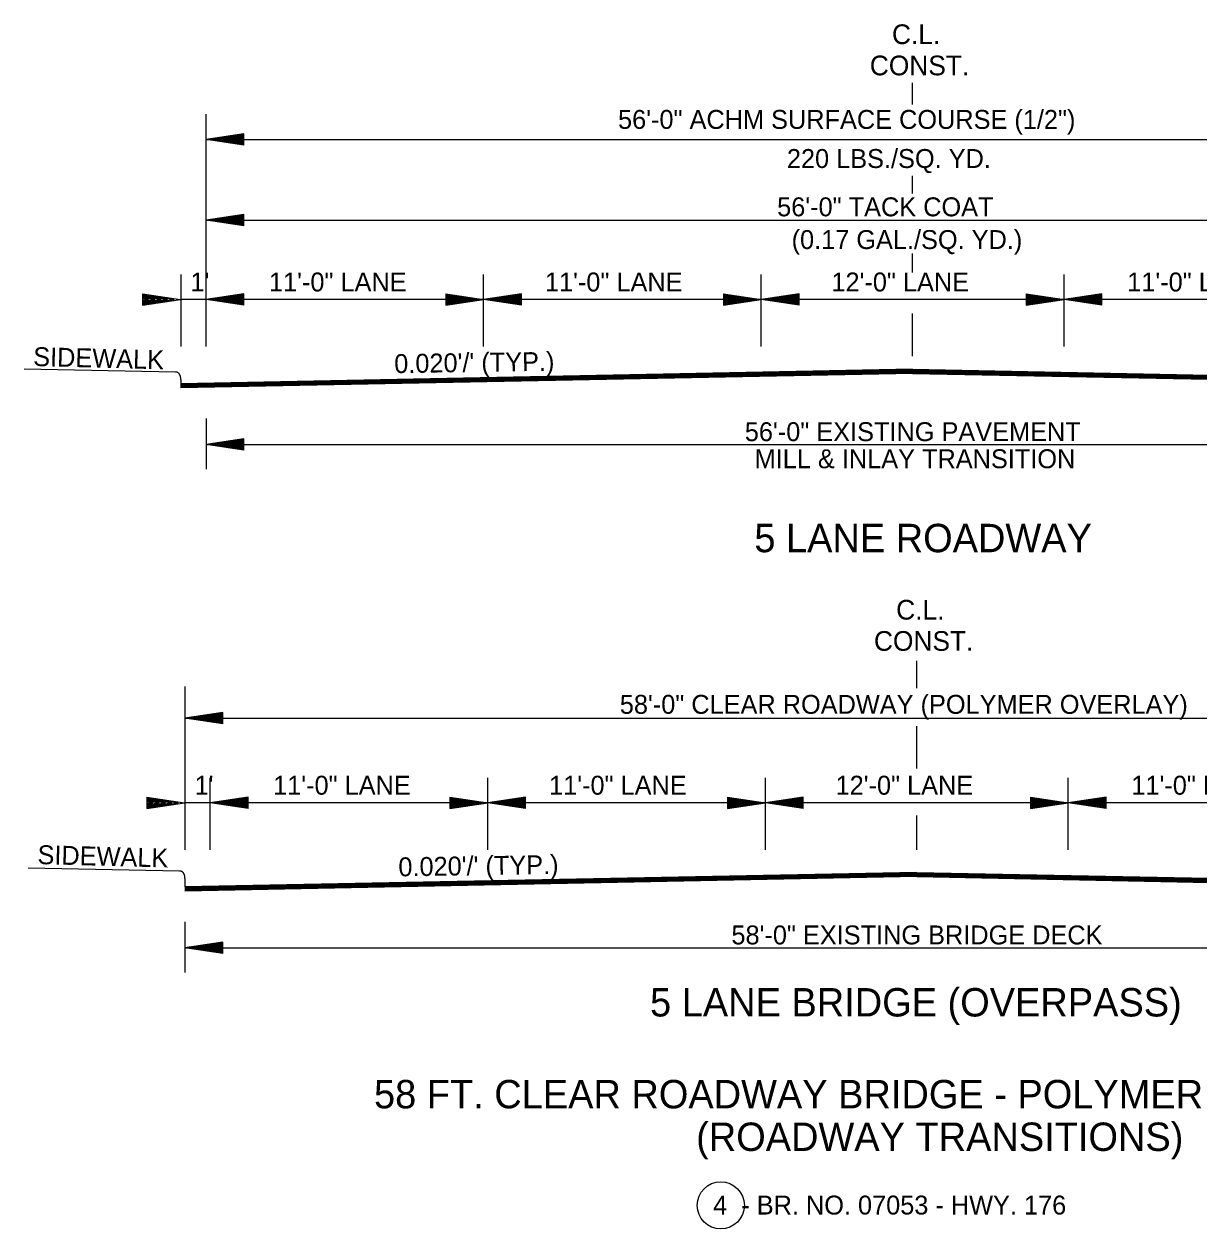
# Model space of a CAD drawing. Extents: x 544199 to 1930787, y -1968972 to 596640.
# Drawn here: x 546380.5 to 546846, y -1949089.3 to -1948612 of the extents above; entities that cross this region are included whole.
import ezdxf

# ---------------------------------------------------------------- set-up
doc = ezdxf.new("R2010")
doc.units = 0
doc.layers.add('R_Border', color=7, linetype='Continuous')
doc.layers.add('R_Draft', color=7, linetype='Continuous')

msp = doc.modelspace()

# ---------------------------------------------------------------- linework, layer by layer
at = {"layer": 'R_Border'}
for p, q in [((546440.43, -1948749.86), (546380.49, -1948748.73)), ((546442.07, -1948947.55), (546382.13, -1948946.43))]:
    msp.add_line(p, q, dxfattribs=at)
msp.add_circle((546656.55, -1949080), 9.34, dxfattribs=at)
for points in [[(546442.58, -1948752.84), (546442.5, -1948749.9), (546440.43, -1948749.86)], [(546444.22, -1948950.54), (546444.14, -1948947.59), (546442.07, -1948947.55)]]:
    msp.add_open_spline(points, degree=2, dxfattribs=at)
at = {"layer": 'R_Draft'}
for p, q in [((546732.58, -1948643.93), (546732.58, -1948635.31)), ((546452.58, -1948739.77), (546452.58, -1948647.75)), ((546467.58, -1948655.51), (546452.58, -1948657.76)), ((546467.58, -1948655.89), (546455.09, -1948657.76)), ((546467.58, -1948656.27), (546457.67, -1948657.76)), ((546467.58, -1948656.65), (546460.16, -1948657.76)), ((546467.58, -1948657.03), (546462.71, -1948657.76)), ((546467.58, -1948657.41), (546465.21, -1948657.76)), ((546467.58, -1948660.01), (546467.58, -1948655.51)), ((546452.58, -1948657.76), (547012.58, -1948657.76)), ((546467.58, -1948660.01), (546452.58, -1948657.76)), ((546467.58, -1948659.64), (546455.09, -1948657.76)), ((546467.58, -1948659.26), (546457.67, -1948657.76)), ((546467.58, -1948658.88), (546460.16, -1948657.76)), ((546467.58, -1948658.49), (546462.71, -1948657.76)), ((546467.58, -1948658.12), (546465.21, -1948657.76)), ((546732.58, -1948679.11), (546732.58, -1948672.11)), ((546467.58, -1948687.41), (546452.58, -1948689.66)), ((546452.58, -1948689.66), (547012.58, -1948689.66)), ((546467.58, -1948691.91), (546452.58, -1948689.66)), ((546467.58, -1948687.79), (546455.09, -1948689.66)), ((546467.58, -1948691.54), (546455.09, -1948689.66)), ((546467.58, -1948688.17), (546457.67, -1948689.66)), ((546467.58, -1948691.16), (546457.67, -1948689.66)), ((546467.58, -1948688.55), (546460.16, -1948689.66)), ((546467.58, -1948690.78), (546460.16, -1948689.66)), ((546467.58, -1948688.93), (546462.71, -1948689.66)), ((546467.58, -1948690.39), (546462.71, -1948689.66)), ((546467.58, -1948689.31), (546465.21, -1948689.66)), ((546467.58, -1948690.02), (546465.21, -1948689.66)), ((546467.58, -1948691.91), (546467.58, -1948687.41)), ((546732.58, -1948710.44), (546732.58, -1948702.92)), ((546442.58, -1948711.22), (546442.58, -1948739.77)), ((546562.58, -1948739.77), (546562.58, -1948711.22)), ((546672.58, -1948739.77), (546672.58, -1948711.22)), ((546792.58, -1948739.77), (546792.58, -1948711.22)), ((546427.46, -1948718.86), (546442.46, -1948721.11)), ((546427.46, -1948718.86), (546427.46, -1948723.36)), ((546427.46, -1948719.23), (546439.95, -1948721.11)), ((546467.58, -1948718.86), (546452.58, -1948721.11)), ((546467.58, -1948719.23), (546455.09, -1948721.11)), ((546467.58, -1948723.36), (546467.58, -1948718.86)), ((546547.58, -1948718.86), (546562.58, -1948721.11)), ((546547.58, -1948718.86), (546547.58, -1948723.36)), ((546547.58, -1948719.23), (546560.08, -1948721.11)), ((546577.58, -1948718.86), (546562.58, -1948721.11)), ((546577.58, -1948719.23), (546565.09, -1948721.11)), ((546577.58, -1948723.36), (546577.58, -1948718.86)), ((546657.58, -1948718.86), (546672.58, -1948721.11)), ((546657.58, -1948718.86), (546657.58, -1948723.36)), ((546657.58, -1948719.23), (546670.08, -1948721.11)), ((546687.58, -1948718.86), (546672.58, -1948721.11)), ((546687.58, -1948719.23), (546675.09, -1948721.11)), ((546687.58, -1948723.36), (546687.58, -1948718.86)), ((546777.58, -1948718.86), (546792.58, -1948721.11)), ((546777.58, -1948718.86), (546777.58, -1948723.36)), ((546777.58, -1948719.23), (546790.08, -1948721.11)), ((546807.58, -1948718.86), (546792.58, -1948721.11)), ((546807.58, -1948719.23), (546795.09, -1948721.11)), ((546807.58, -1948723.36), (546807.58, -1948718.86)), ((546427.46, -1948719.62), (546437.37, -1948721.11)), ((546427.46, -1948719.99), (546434.87, -1948721.11)), ((546427.46, -1948720.38), (546432.33, -1948721.11)), ((546427.46, -1948720.76), (546429.83, -1948721.11)), ((546427.46, -1948723.36), (546442.46, -1948721.11)), ((546427.46, -1948721.84), (546432.33, -1948721.11)), ((546427.46, -1948722.6), (546437.37, -1948721.11)), ((546427.46, -1948722.98), (546439.95, -1948721.11)), ((546427.46, -1948722.23), (546434.87, -1948721.11)), ((546427.46, -1948721.46), (546429.83, -1948721.11)), ((546542.58, -1948721.11), (546442.58, -1948721.11)), ((546467.58, -1948723.36), (546452.58, -1948721.11)), ((546467.58, -1948722.98), (546455.09, -1948721.11)), ((546467.58, -1948719.62), (546457.67, -1948721.11)), ((546467.58, -1948722.6), (546457.67, -1948721.11)), ((546467.58, -1948719.99), (546460.16, -1948721.11)), ((546467.58, -1948722.23), (546460.16, -1948721.11)), ((546467.58, -1948720.37), (546462.71, -1948721.11)), ((546467.58, -1948721.84), (546462.71, -1948721.11)), ((546467.58, -1948720.76), (546465.21, -1948721.11)), ((546467.58, -1948721.46), (546465.21, -1948721.11)), ((546672.58, -1948721.11), (546542.58, -1948721.11)), ((546547.58, -1948719.62), (546557.5, -1948721.11)), ((546547.58, -1948719.99), (546555, -1948721.11)), ((546547.58, -1948720.38), (546552.46, -1948721.11)), ((546547.58, -1948720.76), (546549.95, -1948721.11)), ((546547.58, -1948723.36), (546562.58, -1948721.11)), ((546547.58, -1948721.84), (546552.46, -1948721.11)), ((546547.58, -1948722.6), (546557.5, -1948721.11)), ((546547.58, -1948722.98), (546560.08, -1948721.11)), ((546547.58, -1948722.23), (546555, -1948721.11)), ((546547.58, -1948721.46), (546549.95, -1948721.11)), ((546577.58, -1948723.36), (546562.58, -1948721.11)), ((546577.58, -1948722.98), (546565.09, -1948721.11)), ((546577.58, -1948719.62), (546567.67, -1948721.11)), ((546577.58, -1948722.6), (546567.67, -1948721.11)), ((546577.58, -1948719.99), (546570.16, -1948721.11)), ((546577.58, -1948722.23), (546570.16, -1948721.11)), ((546577.58, -1948720.37), (546572.71, -1948721.11)), ((546577.58, -1948721.84), (546572.71, -1948721.11)), ((546577.58, -1948720.76), (546575.21, -1948721.11)), ((546577.58, -1948721.46), (546575.21, -1948721.11)), ((546657.58, -1948719.62), (546667.5, -1948721.11)), ((546657.58, -1948719.99), (546665, -1948721.11)), ((546657.58, -1948720.38), (546662.46, -1948721.11)), ((546657.58, -1948720.76), (546659.95, -1948721.11)), ((546657.58, -1948723.36), (546672.58, -1948721.11)), ((546657.58, -1948721.84), (546662.46, -1948721.11)), ((546657.58, -1948722.6), (546667.5, -1948721.11)), ((546657.58, -1948722.98), (546670.08, -1948721.11)), ((546657.58, -1948722.23), (546665, -1948721.11)), ((546657.58, -1948721.46), (546659.95, -1948721.11)), ((546792.58, -1948721.11), (546672.58, -1948721.11)), ((546687.58, -1948723.36), (546672.58, -1948721.11)), ((546687.58, -1948722.98), (546675.09, -1948721.11)), ((546687.58, -1948719.62), (546677.67, -1948721.11)), ((546687.58, -1948722.6), (546677.67, -1948721.11)), ((546687.58, -1948719.99), (546680.16, -1948721.11)), ((546687.58, -1948722.23), (546680.16, -1948721.11)), ((546687.58, -1948720.37), (546682.71, -1948721.11)), ((546687.58, -1948721.84), (546682.71, -1948721.11)), ((546687.58, -1948720.76), (546685.21, -1948721.11)), ((546687.58, -1948721.46), (546685.21, -1948721.11)), ((546777.58, -1948719.62), (546787.5, -1948721.11)), ((546777.58, -1948719.99), (546785, -1948721.11)), ((546777.58, -1948720.38), (546782.46, -1948721.11)), ((546777.58, -1948720.76), (546779.95, -1948721.11)), ((546777.58, -1948723.36), (546792.58, -1948721.11)), ((546777.58, -1948721.84), (546782.46, -1948721.11)), ((546777.58, -1948722.6), (546787.5, -1948721.11)), ((546777.58, -1948722.98), (546790.08, -1948721.11)), ((546777.58, -1948722.23), (546785, -1948721.11)), ((546777.58, -1948721.46), (546779.95, -1948721.11)), ((546922.58, -1948721.11), (546792.58, -1948721.11)), ((546807.58, -1948723.36), (546792.58, -1948721.11)), ((546807.58, -1948722.98), (546795.09, -1948721.11)), ((546807.58, -1948719.62), (546797.67, -1948721.11)), ((546807.58, -1948722.6), (546797.67, -1948721.11)), ((546807.58, -1948719.99), (546800.16, -1948721.11)), ((546807.58, -1948722.23), (546800.16, -1948721.11)), ((546807.58, -1948720.37), (546802.71, -1948721.11)), ((546807.58, -1948721.84), (546802.71, -1948721.11)), ((546807.58, -1948720.76), (546805.21, -1948721.11)), ((546807.58, -1948721.46), (546805.21, -1948721.11)), ((546732.58, -1948743.55), (546732.58, -1948726.65)), ((546732.58, -1948748.72), (546442.58, -1948754.52)), ((546732.59, -1948749.02), (546442.58, -1948754.82)), ((546732.59, -1948749.32), (546442.58, -1948755.12)), ((546732.6, -1948749.62), (546442.58, -1948755.42)), ((546732.6, -1948749.92), (546442.58, -1948755.72)), ((546732.61, -1948750.22), (546442.58, -1948756.02)), ((546732.61, -1948750.39), (546442.58, -1948756.19)), ((546442.58, -1948752.84), (546442.58, -1948754.52)), ((546732.55, -1948750.22), (547022.58, -1948756.02)), ((546732.55, -1948750.39), (547022.58, -1948756.19)), ((546732.56, -1948749.62), (547022.58, -1948755.42)), ((546732.56, -1948749.92), (547022.58, -1948755.72)), ((546732.57, -1948749.02), (547022.58, -1948754.82)), ((546732.57, -1948749.32), (547022.58, -1948755.12)), ((546732.58, -1948748.72), (547022.58, -1948754.52)), ((546442.58, -1948754.52), (546442.58, -1948756.19)), ((546452.61, -1948768.32), (546452.61, -1948788.32)), ((546467.58, -1948776.32), (546452.58, -1948778.57)), ((546467.58, -1948776.7), (546455.09, -1948778.57)), ((546467.58, -1948780.82), (546467.58, -1948776.32)), ((546452.58, -1948778.57), (547012.58, -1948778.57)), ((546467.58, -1948780.82), (546452.58, -1948778.57)), ((546467.58, -1948780.45), (546455.09, -1948778.57)), ((546467.58, -1948777.08), (546457.67, -1948778.57)), ((546467.58, -1948780.07), (546457.67, -1948778.57)), ((546467.58, -1948777.46), (546460.16, -1948778.57)), ((546467.58, -1948779.69), (546460.16, -1948778.57)), ((546467.58, -1948777.84), (546462.71, -1948778.57)), ((546467.58, -1948779.3), (546462.71, -1948778.57)), ((546467.58, -1948778.22), (546465.21, -1948778.57)), ((546467.58, -1948778.93), (546465.21, -1948778.57)), ((546734.22, -1948875.08), (546734.22, -1948864.22)), ((546444.22, -1948874.41), (546444.22, -1948939.14)), ((546459.22, -1948884.69), (546444.22, -1948886.94)), ((546459.22, -1948885.06), (546446.73, -1948886.94)), ((546459.22, -1948885.45), (546449.31, -1948886.94)), ((546459.22, -1948885.82), (546451.81, -1948886.94)), ((546459.22, -1948886.2), (546454.35, -1948886.94)), ((546459.22, -1948886.59), (546456.85, -1948886.94)), ((546459.22, -1948889.19), (546459.22, -1948884.69)), ((546444.22, -1948886.94), (547024.22, -1948886.94)), ((546459.22, -1948889.19), (546444.22, -1948886.94)), ((546459.22, -1948888.81), (546446.73, -1948886.94)), ((546459.22, -1948888.43), (546449.31, -1948886.94)), ((546459.22, -1948888.06), (546451.81, -1948886.94)), ((546459.22, -1948887.67), (546454.35, -1948886.94)), ((546459.22, -1948887.29), (546456.85, -1948886.94)), ((546734.22, -1948907), (546734.22, -1948890.1)), ((546454.22, -1948939.14), (546454.22, -1948910.58)), ((546564.22, -1948939.14), (546564.22, -1948910.58)), ((546674.22, -1948939.14), (546674.22, -1948910.58)), ((546794.22, -1948939.14), (546794.22, -1948910.58)), ((546429.1, -1948918.23), (546444.1, -1948920.48)), ((546429.1, -1948918.23), (546429.1, -1948922.73)), ((546429.1, -1948918.6), (546441.59, -1948920.48)), ((546429.1, -1948918.98), (546439.01, -1948920.48)), ((546429.1, -1948919.36), (546436.52, -1948920.48)), ((546429.1, -1948919.75), (546433.97, -1948920.48)), ((546469.22, -1948918.23), (546454.22, -1948920.48)), ((546469.22, -1948918.6), (546456.73, -1948920.48)), ((546469.22, -1948918.98), (546459.31, -1948920.48)), ((546469.22, -1948919.36), (546461.81, -1948920.48)), ((546469.22, -1948919.74), (546464.35, -1948920.48)), ((546469.22, -1948922.73), (546469.22, -1948918.23)), ((546549.22, -1948918.23), (546564.22, -1948920.48)), ((546549.22, -1948918.23), (546549.22, -1948922.73)), ((546549.22, -1948918.6), (546561.72, -1948920.48)), ((546549.22, -1948918.98), (546559.14, -1948920.48)), ((546549.22, -1948919.36), (546556.64, -1948920.48)), ((546549.22, -1948919.75), (546554.1, -1948920.48)), ((546579.22, -1948918.23), (546564.22, -1948920.48)), ((546579.22, -1948918.6), (546566.73, -1948920.48)), ((546579.22, -1948918.98), (546569.31, -1948920.48)), ((546579.22, -1948919.36), (546571.81, -1948920.48)), ((546579.22, -1948919.74), (546574.35, -1948920.48)), ((546579.22, -1948922.73), (546579.22, -1948918.23)), ((546659.22, -1948918.23), (546674.22, -1948920.48)), ((546659.22, -1948918.23), (546659.22, -1948922.73)), ((546659.22, -1948918.6), (546671.72, -1948920.48)), ((546659.22, -1948918.98), (546669.14, -1948920.48)), ((546659.22, -1948919.36), (546666.64, -1948920.48)), ((546659.22, -1948919.75), (546664.1, -1948920.48)), ((546689.22, -1948918.23), (546674.22, -1948920.48)), ((546689.22, -1948918.6), (546676.73, -1948920.48)), ((546689.22, -1948918.98), (546679.31, -1948920.48)), ((546689.22, -1948919.36), (546681.81, -1948920.48)), ((546689.22, -1948919.74), (546684.35, -1948920.48)), ((546689.22, -1948922.73), (546689.22, -1948918.23)), ((546779.22, -1948918.23), (546794.22, -1948920.48)), ((546779.22, -1948918.23), (546779.22, -1948922.73)), ((546779.22, -1948918.6), (546791.72, -1948920.48)), ((546779.22, -1948918.98), (546789.14, -1948920.48)), ((546779.22, -1948919.36), (546786.64, -1948920.48)), ((546779.22, -1948919.75), (546784.1, -1948920.48)), ((546809.22, -1948918.23), (546794.22, -1948920.48)), ((546809.22, -1948918.6), (546796.73, -1948920.48)), ((546809.22, -1948918.98), (546799.31, -1948920.48)), ((546809.22, -1948919.36), (546801.81, -1948920.48)), ((546809.22, -1948919.74), (546804.35, -1948920.48)), ((546809.22, -1948922.73), (546809.22, -1948918.23)), ((546429.1, -1948920.12), (546431.47, -1948920.48)), ((546429.1, -1948922.73), (546444.1, -1948920.48)), ((546429.1, -1948921.21), (546433.97, -1948920.48)), ((546429.1, -1948921.97), (546439.01, -1948920.48)), ((546429.1, -1948922.35), (546441.59, -1948920.48)), ((546429.1, -1948921.59), (546436.52, -1948920.48)), ((546429.1, -1948920.83), (546431.47, -1948920.48)), ((546544.22, -1948920.48), (546444.22, -1948920.48)), ((546469.22, -1948922.73), (546454.22, -1948920.48)), ((546469.22, -1948922.35), (546456.73, -1948920.48)), ((546469.22, -1948921.97), (546459.31, -1948920.48)), ((546469.22, -1948921.59), (546461.81, -1948920.48)), ((546469.22, -1948921.2), (546464.35, -1948920.48)), ((546469.22, -1948920.12), (546466.85, -1948920.48)), ((546469.22, -1948920.83), (546466.85, -1948920.48)), ((546674.22, -1948920.48), (546544.22, -1948920.48)), ((546549.22, -1948920.12), (546551.59, -1948920.48)), ((546549.22, -1948922.73), (546564.22, -1948920.48)), ((546549.22, -1948921.21), (546554.1, -1948920.48)), ((546549.22, -1948921.97), (546559.14, -1948920.48)), ((546549.22, -1948922.35), (546561.72, -1948920.48)), ((546549.22, -1948921.59), (546556.64, -1948920.48)), ((546549.22, -1948920.83), (546551.59, -1948920.48)), ((546579.22, -1948922.73), (546564.22, -1948920.48)), ((546579.22, -1948922.35), (546566.73, -1948920.48)), ((546579.22, -1948921.97), (546569.31, -1948920.48)), ((546579.22, -1948921.59), (546571.81, -1948920.48)), ((546579.22, -1948921.2), (546574.35, -1948920.48)), ((546579.22, -1948920.12), (546576.85, -1948920.48)), ((546579.22, -1948920.83), (546576.85, -1948920.48)), ((546659.22, -1948920.12), (546661.59, -1948920.48)), ((546659.22, -1948922.73), (546674.22, -1948920.48)), ((546659.22, -1948921.21), (546664.1, -1948920.48)), ((546659.22, -1948921.97), (546669.14, -1948920.48)), ((546659.22, -1948922.35), (546671.72, -1948920.48)), ((546659.22, -1948921.59), (546666.64, -1948920.48)), ((546659.22, -1948920.83), (546661.59, -1948920.48)), ((546794.22, -1948920.48), (546674.22, -1948920.48)), ((546689.22, -1948922.73), (546674.22, -1948920.48)), ((546689.22, -1948922.35), (546676.73, -1948920.48)), ((546689.22, -1948921.97), (546679.31, -1948920.48)), ((546689.22, -1948921.59), (546681.81, -1948920.48)), ((546689.22, -1948921.2), (546684.35, -1948920.48)), ((546689.22, -1948920.12), (546686.85, -1948920.48)), ((546689.22, -1948920.83), (546686.85, -1948920.48)), ((546779.22, -1948920.12), (546781.59, -1948920.48)), ((546779.22, -1948922.73), (546794.22, -1948920.48)), ((546779.22, -1948921.21), (546784.1, -1948920.48)), ((546779.22, -1948921.97), (546789.14, -1948920.48)), ((546779.22, -1948922.35), (546791.72, -1948920.48)), ((546779.22, -1948921.59), (546786.64, -1948920.48)), ((546779.22, -1948920.83), (546781.59, -1948920.48)), ((546924.22, -1948920.48), (546794.22, -1948920.48)), ((546809.22, -1948922.73), (546794.22, -1948920.48)), ((546809.22, -1948922.35), (546796.73, -1948920.48)), ((546809.22, -1948921.97), (546799.31, -1948920.48)), ((546809.22, -1948921.59), (546801.81, -1948920.48)), ((546809.22, -1948921.2), (546804.35, -1948920.48)), ((546809.22, -1948920.12), (546806.85, -1948920.48)), ((546809.22, -1948920.83), (546806.85, -1948920.48)), ((546734.22, -1948939.14), (546734.22, -1948925.55)), ((546734.22, -1948948.08), (546444.22, -1948953.88)), ((546734.23, -1948948.38), (546444.22, -1948954.18)), ((546734.24, -1948948.68), (546444.22, -1948954.48)), ((546734.21, -1948948.68), (547024.22, -1948954.48)), ((546734.22, -1948948.08), (547024.22, -1948953.88)), ((546734.22, -1948948.38), (547024.22, -1948954.18)), ((546734.24, -1948948.98), (546444.22, -1948954.78)), ((546734.25, -1948949.28), (546444.22, -1948955.08)), ((546734.25, -1948949.58), (546444.22, -1948955.38)), ((546734.26, -1948949.75), (546444.22, -1948955.55)), ((546444.22, -1948950.54), (546444.22, -1948952.21)), ((546444.22, -1948952.21), (546444.22, -1948953.88)), ((546734.19, -1948949.58), (547024.22, -1948955.38)), ((546734.19, -1948949.75), (547024.22, -1948955.55)), ((546734.2, -1948949.28), (547024.22, -1948955.08)), ((546734.21, -1948948.98), (547024.22, -1948954.78)), ((546444.22, -1948967.69), (546444.22, -1948987.69)), ((546459.22, -1948975.69), (546444.22, -1948977.94)), ((546459.22, -1948976.07), (546446.73, -1948977.94)), ((546459.22, -1948976.45), (546449.31, -1948977.94)), ((546459.22, -1948976.82), (546451.81, -1948977.94)), ((546459.22, -1948977.21), (546454.35, -1948977.94)), ((546459.22, -1948980.19), (546459.22, -1948975.69)), ((546444.22, -1948977.94), (547024.22, -1948977.94)), ((546459.22, -1948980.19), (546444.22, -1948977.94)), ((546459.22, -1948979.82), (546446.73, -1948977.94)), ((546459.22, -1948979.43), (546449.31, -1948977.94)), ((546459.22, -1948979.06), (546451.81, -1948977.94)), ((546459.22, -1948978.67), (546454.35, -1948977.94)), ((546459.22, -1948977.59), (546456.85, -1948977.94)), ((546459.22, -1948978.29), (546456.85, -1948977.94))]:
    msp.add_line(p, q, dxfattribs=at)

# ---------------------------------------------------------------- texts
for s, height, p in [('C.L.', 7.8, (546724.39, -1948619.94)), ('CONST.', 7.8, (546715.61, -1948632.31)), ('56\'-0" ACHM SURFACE COURSE (1/2")', 7.5, (546615.84, -1948653.54)), ('220 LBS./SQ. YD. ', 7.5, (546682.75, -1948669.03)), ('56\'-0" TACK COAT', 7.5, (546678.89, -1948688.17)), ('(0.17 GAL./SQ. YD.)', 7.5, (546684.62, -1948701.14)), ("1'", 7.5, (546446.41, -1948717.94)), ('11\'-0" LANE', 7.5, (546477.52, -1948717.94)), ('11\'-0" LANE', 7.5, (546586.87, -1948717.94)), ('12\'-0" LANE', 7.5, (546700.4, -1948717.94)), ('11\'-0" LANE', 7.5, (546817.61, -1948717.94)), ('56\'-0" EXISTING PAVEMENT', 7.5, (546666.08, -1948777.25)), ('MILL & INLAY TRANSITION', 7.5, (546669.97, -1948787.97)), ('5 LANE ROADWAY', 11.25, (546669.85, -1948821.25)), ('C.L.', 7.8, (546726.04, -1948847.94)), ('CONST.', 7.8, (546717.25, -1948860.31)), ('58\'-0" CLEAR ROADWAY (POLYMER OVERLAY)', 7.5, (546616.55, -1948885.27)), ("1'", 7.5, (546448.06, -1948917.31)), ('11\'-0" LANE', 7.5, (546479.16, -1948917.31)), ('11\'-0" LANE', 7.5, (546588.51, -1948917.31)), ('12\'-0" LANE', 7.5, (546702.04, -1948917.31)), ('11\'-0" LANE', 7.5, (546819.25, -1948917.31)), ('58\'-0" EXISTING BRIDGE DECK', 7.5, (546660.78, -1948976.62)), ('5 LANE BRIDGE (OVERPASS)', 11.25, (546628.53, -1949005.18)), ('58 FT. CLEAR ROADWAY BRIDGE - POLYMER OVERLAY', 11.25, (546519.15, -1949041.57)), ('(ROADWAY TRANSITIONS)', 11.25, (546646.79, -1949058.45)), ('4  - BR. NO. 07053 - HWY. 176', 7.5, (546653.53, -1949083.64))]:
    msp.add_text(s, height=height, dxfattribs=at).set_placement(p)
for s, rotation, p in [('SIDEWALK', 358.5287, (546384.02, -1948747.47)), ("0.020'/' (TYP.)", 0.8719, (546527.22, -1948750.31)), ('SIDEWALK', 358.4674, (546385.73, -1948944.78)), ("0.020'/' (TYP.)", 0.8719, (546528.86, -1948949.68))]:
    msp.add_text(s, height=7.5, rotation=rotation, dxfattribs=at).set_placement(p)

doc.saveas('drawing.dxf')
